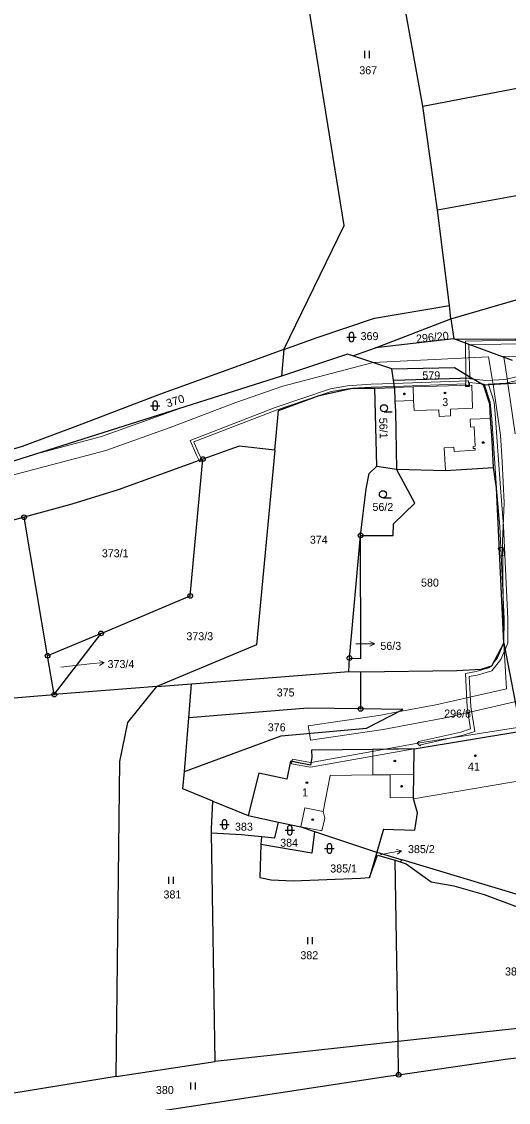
# Model space of a CAD drawing. Extents: x -769392 to -767038, y -1018329 to -1015269.
# Drawn here: x -768677.7 to -768574.3, y -1016436.2 to -1016206.6 of the extents above; entities that cross this region are included whole.
import ezdxf
from ezdxf.enums import TextEntityAlignment as Align

# ---------------------------------------------------------------- set-up
doc = ezdxf.new("R2010")
doc.units = 0
doc.header["$LTSCALE"] = 0.68
for name, color, linetype, lineweight in [('1', 7, 'Continuous', 25), ('13', 7, 'Continuous', 13), ('3', 7, 'Continuous', 25), ('4', 7, 'Continuous', 13), ('5', 7, 'Continuous', 25), ('7', 7, 'Continuous', 13), ('8', 7, 'Continuous', 25)]:
    doc.layers.add(name, color=color, linetype=linetype, lineweight=lineweight)
doc.layers.add('2', color=7, linetype='Continuous')

msp = doc.modelspace()

# ---------------------------------------------------------------- linework, layer by layer
at = {"layer": '1'}
for p, q in [((-768592.42, -1016224.53), (-768596.46, -1016202.24)), ((-768592.42, -1016224.53), (-768551.7, -1016216.69)), ((-768589.35, -1016246.59), (-768592.42, -1016224.53)), ((-768557.84, -1016240.9), (-768589.35, -1016246.59)), ((-768586.82, -1016266.89), (-768589.35, -1016246.59)), ((-768586.47, -1016269.73), (-768586.82, -1016266.89)), ((-768586.47, -1016269.73), (-768572.62, -1016265.7)), ((-768602.49, -1016275.85), (-768586.47, -1016269.73)), ((-768586.47, -1016269.73), (-768585.84, -1016273.96)), ((-768585.84, -1016273.96), (-768602.49, -1016275.85)), ((-768573.42, -1016278.56), (-768585.84, -1016273.96)), ((-768585.84, -1016273.96), (-768559.15, -1016274.1)), ((-768621.96, -1016276.21), (-768622.48, -1016281.86)), ((-768607.35, -1016277.6), (-768602.49, -1016275.85)), ((-768599.04, -1016280.32), (-768607.35, -1016277.6)), ((-768599.04, -1016280.32), (-768585.73, -1016280.07)), ((-768598.72, -1016282.72), (-768599.04, -1016280.32)), ((-768585.73, -1016280.07), (-768582.11, -1016282.22)), ((-768598.72, -1016282.72), (-768582.11, -1016282.22)), ((-768598.51, -1016284.32), (-768598.72, -1016282.72)), ((-768582.11, -1016282.22), (-768579.53, -1016283.75)), ((-768579.53, -1016283.75), (-768569.79, -1016283.19)), ((-768602.65, -1016284.41), (-768598.51, -1016284.32)), ((-768602.24, -1016301.02), (-768602.65, -1016284.41)), ((-768598.51, -1016284.32), (-768598.39, -1016287.19)), ((-768578.2, -1016287.85), (-768579.53, -1016283.75)), ((-768598.39, -1016287.19), (-768598.28, -1016289.32)), ((-768578.09, -1016290.87), (-768578.2, -1016287.85)), ((-768598.28, -1016289.32), (-768598.05, -1016301.67)), ((-768577.73, -1016295.5), (-768578.09, -1016290.87)), ((-768631.49, -1016296.74), (-768639.19, -1016299.52)), ((-768623.94, -1016297.62), (-768631.49, -1016296.74)), ((-768577.47, -1016301.28), (-768577.73, -1016295.5)), ((-768639.19, -1016299.52), (-768657.22, -1016306.04)), ((-768641.88, -1016328.59), (-768639.19, -1016299.52)), ((-768602.24, -1016301.02), (-768598.05, -1016301.67)), ((-768598.05, -1016301.67), (-768587.63, -1016301.96)), ((-768594.12, -1016308.89), (-768598.05, -1016301.67)), ((-768587.63, -1016301.96), (-768577.47, -1016301.28)), ((-768576.83, -1016305.58), (-768577.47, -1016301.28)), ((-768657.22, -1016306.04), (-768667.08, -1016309.08)), ((-768575.23, -1016338.61), (-768576.83, -1016305.58)), ((-768667.08, -1016309.08), (-768677.21, -1016311.87)), ((-768598.68, -1016313.23), (-768594.12, -1016308.89)), ((-768677.21, -1016311.87), (-768686.93, -1016314.55)), ((-768672.19, -1016341.29), (-768677.21, -1016311.87)), ((-768598.78, -1016315.77), (-768598.68, -1016313.23)), ((-768608.05, -1016341.79), (-768605.68, -1016315.72)), ((-768605.68, -1016315.72), (-768598.78, -1016315.77)), ((-768605.62, -1016341.85), (-768605.68, -1016315.72)), ((-768660.84, -1016336.55), (-768641.88, -1016328.59)), ((-768660.84, -1016336.55), (-768672.19, -1016341.29)), ((-768670.77, -1016349.54), (-768660.84, -1016336.55)), ((-768577.76, -1016343.44), (-768575.23, -1016338.61)), ((-768575.23, -1016338.61), (-768571.6, -1016357.31)), ((-768670.77, -1016349.54), (-768672.19, -1016341.29)), ((-768608.18, -1016344.65), (-768608.05, -1016341.79)), ((-768608.05, -1016341.79), (-768605.62, -1016341.85)), ((-768641.59, -1016347.26), (-768608.18, -1016344.65)), ((-768608.18, -1016344.65), (-768605.68, -1016344.71)), ((-768605.68, -1016344.71), (-768605.69, -1016352.6)), ((-768605.68, -1016344.71), (-768585.23, -1016344.42)), ((-768585.23, -1016344.42), (-768580.06, -1016344.17)), ((-768580.06, -1016344.17), (-768577.76, -1016343.44)), ((-768648.98, -1016347.83), (-768641.59, -1016347.26)), ((-768642.16, -1016354.47), (-768641.59, -1016347.26)), ((-768712.03, -1016352.77), (-768670.77, -1016349.54)), ((-768648.98, -1016347.83), (-768670.77, -1016349.54)), ((-768643.08, -1016365.89), (-768642.16, -1016354.47)), ((-768594.29, -1016361.09), (-768571.6, -1016357.31)), ((-768603.09, -1016361.21), (-768616.13, -1016361.33)), ((-768616.13, -1016361.33), (-768616.02, -1016362.93)), ((-768594.29, -1016361.09), (-768603.09, -1016361.21)), ((-768594.38, -1016366.52), (-768594.29, -1016361.09)), ((-768620.57, -1016363.7), (-768621.35, -1016367.52)), ((-768616.32, -1016364.51), (-768620.57, -1016363.7)), ((-768616.02, -1016362.93), (-768616.32, -1016364.51)), ((-768627.31, -1016366.26), (-768629.54, -1016375.23)), ((-768621.35, -1016367.52), (-768627.31, -1016366.26)), ((-768594.46, -1016371.32), (-768594.38, -1016366.52)), ((-768637.05, -1016372.2), (-768629.54, -1016375.23)), ((-768594.45, -1016371.67), (-768594.46, -1016371.32)), ((-768593.61, -1016374.68), (-768594.45, -1016371.67)), ((-768629.54, -1016375.23), (-768623.13, -1016376.62)), ((-768594.12, -1016378.36), (-768593.61, -1016374.68)), ((-768623.13, -1016376.62), (-768618.4, -1016377.64)), ((-768618.4, -1016377.64), (-768615.5, -1016378.61)), ((-768636.6, -1016427.52), (-768637.35, -1016378.93)), ((-768626.73, -1016379.72), (-768626.91, -1016381.42)), ((-768615.5, -1016378.61), (-768602.49, -1016382.96)), ((-768600.8, -1016378.13), (-768602.21, -1016383.04)), ((-768600.8, -1016378.13), (-768594.12, -1016378.36)), ((-768602.21, -1016383.04), (-768603.78, -1016388.43)), ((-768602.49, -1016382.96), (-768602.21, -1016383.04)), ((-768602.21, -1016383.04), (-768596.87, -1016384.66)), ((-768597.72, -1016423.25), (-768598.32, -1016384.76)), ((-768596.87, -1016384.66), (-768597.3, -1016385.07)), ((-768571.23, -1016392.4), (-768596.87, -1016384.66)), ((-768515.42, -1016414.21), (-768597.72, -1016423.25)), ((-768597.72, -1016423.25), (-768636.6, -1016427.52)), ((-768597.61, -1016430.31), (-768597.72, -1016423.25)), ((-768657.6, -1016430.72), (-768636.6, -1016427.52)), ((-768657.6, -1016430.72), (-768699.1, -1016437.44))]:
    msp.add_line(p, q, dxfattribs=at)
for points in [[(-768621.96, -1016276.21), (-768609.16, -1016249.91), (-768617.69, -1016197.27), (-768590.44, -1016160.65)], [(-768621.96, -1016276.21), (-768614.91, -1016273.67), (-768602.73, -1016269.59), (-768586.82, -1016266.89)], [(-768621.96, -1016276.21), (-768630.81, -1016279.41), (-768648.44, -1016285.81), (-768665.84, -1016292.42), (-768677.61, -1016296.82), (-768689.85, -1016300.54), (-768706.04, -1016305.61), (-768723.63, -1016310.87)], [(-768607.35, -1016277.6), (-768608.47, -1016277.23), (-768622.48, -1016281.86)], [(-768622.48, -1016281.86), (-768683.8, -1016301.28), (-768723.63, -1016310.87)], [(-768623.94, -1016297.62), (-768623.16, -1016289.18), (-768614.47, -1016286), (-768607.38, -1016284.46), (-768602.65, -1016284.41)], [(-768623.94, -1016297.62), (-768627.77, -1016338.94), (-768648.98, -1016347.83)], [(-768605.68, -1016315.72), (-768604.47, -1016305.83), (-768603.85, -1016302.57), (-768602.24, -1016301.02)], [(-768657.6, -1016430.72), (-768656.85, -1016363.77), (-768655.17, -1016355.5), (-768648.98, -1016347.83)], [(-768643.08, -1016365.89), (-768622.57, -1016358.32), (-768604.43, -1016356.68), (-768596.71, -1016352.7), (-768605.69, -1016352.6)], [(-768605.69, -1016352.6), (-768616.9, -1016352.46), (-768642.16, -1016354.47)], [(-768637.05, -1016372.2), (-768643.47, -1016369.6), (-768643.08, -1016365.89)], [(-768637.35, -1016378.93), (-768637.36, -1016378.08), (-768637.05, -1016372.2)], [(-768626.73, -1016379.72), (-768623.93, -1016380.01), (-768623.13, -1016376.62)], [(-768637.35, -1016378.93), (-768630.98, -1016379.26), (-768626.73, -1016379.72)], [(-768615.5, -1016378.61), (-768616.02, -1016383.21), (-768626.91, -1016381.42)], [(-768626.91, -1016381.42), (-768627.07, -1016388.41), (-768624.68, -1016388.89), (-768620.01, -1016389.13), (-768605.69, -1016388.54), (-768603.78, -1016388.43)], [(-768603.78, -1016388.43), (-768602.06, -1016383.63), (-768598.32, -1016384.76), (-768597.3, -1016385.07)], [(-768597.3, -1016385.07), (-768595.97, -1016385.47), (-768590.69, -1016389.34), (-768585.89, -1016390.17), (-768579.44, -1016391.99), (-768554.41, -1016401.35), (-768536.99, -1016407.59), (-768527.09, -1016410.45), (-768515.42, -1016414.21)], [(-768597.61, -1016430.31), (-768574.91, -1016427.03), (-768544.97, -1016423.27), (-768527.49, -1016419.91), (-768510.33, -1016417.43)], [(-768697.86, -1016445.59), (-768599.92, -1016430.64), (-768597.61, -1016430.31)]]:
    msp.add_lwpolyline(points, dxfattribs=at)
at = {"layer": '13'}
for points in [[(-768699.64, -1016308.19), (-768659.83, -1016297.71), (-768646.13, -1016292.81), (-768632.17, -1016287.45), (-768622.22, -1016284.01), (-768603.02, -1016279.02), (-768578.47, -1016277.79), (-768577.72, -1016282.36), (-768577.53, -1016283.64), (-768574.38, -1016283.45), (-768574.61, -1016281.88), (-768575.27, -1016277.87), (-768585.84, -1016273.96), (-768602.49, -1016275.85), (-768607.347, -1016277.599), (-768608.47, -1016277.23), (-768622.48, -1016281.86), (-768642.32, -1016288.14), (-768660.75, -1016294.73), (-768674.85, -1016298.44), (-768683.8, -1016301.28)], [(-768572.83, -1016294.11), (-768574.38, -1016283.45), (-768577.53, -1016283.64), (-768575.96, -1016294.45), (-768575.58, -1016300.01), (-768575.19, -1016308.81), (-768575.49, -1016316.99), (-768575.46, -1016323.44), (-768575.28, -1016337.49), (-768575.23, -1016338.61), (-768575.27, -1016338.68), (-768574.67, -1016348.34), (-768589.7, -1016351.7), (-768597.74, -1016353.23), (-768601.41, -1016353.93), (-768616.81, -1016356.18), (-768616.56, -1016357.78), (-768616.33, -1016359.25), (-768600.89, -1016356.99), (-768587.74, -1016354.48), (-768572.31, -1016350.97)], [(-768569.72, -1016281.3), (-768574.97, -1016282.6), (-768579.08, -1016282.81), (-768581.59, -1016282.53), (-768579.91, -1016283.52), (-768579.4, -1016283.58), (-768579.35, -1016283.74), (-768578.52, -1016283.69), (-768578.56, -1016283.58), (-768574.85, -1016283.4), (-768569.87, -1016282.17)], [(-768541.64, -1016351.71), (-768593.54, -1016359.85), (-768600.9, -1016361.18), (-768594.29, -1016361.09), (-768571.6, -1016357.31)]]:
    msp.add_lwpolyline(points, dxfattribs=at)
for points in [[(-768562.71, -1016277.52), (-768560.04, -1016277.46), (-768559.31, -1016277.38), (-768559.15, -1016274.1), (-768585.84, -1016273.96), (-768575.27, -1016277.87), (-768575.3, -1016277.7)], [(-768583.42, -1016274.43), (-768583.41, -1016274.86), (-768582.47, -1016275.21), (-768572.49, -1016275.05), (-768571.9, -1016274.64), (-768571.31, -1016274.6), (-768570.93, -1016274.92), (-768562.98, -1016274.76), (-768562.81, -1016274.11), (-768563.03, -1016274.11), (-768563.02, -1016273.92), (-768563.37, -1016273.91), (-768563.38, -1016274.12), (-768570.5, -1016274.24), (-768571.05, -1016273.78), (-768572.17, -1016273.86), (-768572.75, -1016274.25)], [(-768583.41, -1016274.86), (-768583.32, -1016281.5), (-768582.45, -1016282.02), (-768582.66, -1016275.21), (-768582.47, -1016275.21)], [(-768598.62, -1016283.45), (-768603.46, -1016283.62), (-768608.48, -1016283.96), (-768612.1, -1016284.57), (-768623.84, -1016288.56), (-768641.89, -1016295.53), (-768640.59, -1016298.64), (-768640, -1016299.81), (-768639.43, -1016299.61), (-768640.05, -1016298.39), (-768641.1, -1016295.87), (-768623.63, -1016289.12), (-768614.47, -1016286), (-768611.95, -1016285.15), (-768608.41, -1016284.55), (-768607.38, -1016284.46), (-768603.43, -1016284.22), (-768598.55, -1016284.05)], [(-768598.62, -1016283.45), (-768598.55, -1016284.05), (-768583.3, -1016283.53), (-768583.28, -1016283.86), (-768582.68, -1016283.84), (-768582.75, -1016282.91)], [(-768583.37, -1016284.07), (-768582.56, -1016284.05), (-768582.52, -1016283.23), (-768579.91, -1016283.52), (-768581.59, -1016282.53), (-768582.44, -1016282.43), (-768582.45, -1016282.02), (-768583.32, -1016281.5), (-768583.3, -1016282.76)], [(-768579.35, -1016283.74), (-768578.14, -1016287.43), (-768577.78, -1016290.99), (-768576.77, -1016305.69), (-768576.1, -1016313.83), (-768575.19, -1016333.44), (-768575.21, -1016338.45), (-768575.23, -1016338.51), (-768575.23, -1016338.61), (-768575.46, -1016339.06), (-768576.57, -1016341.7), (-768577.36, -1016342.68), (-768577.76, -1016343.44), (-768578.05, -1016343.53), (-768578.25, -1016343.78), (-768581.11, -1016344.66), (-768583.42, -1016345.04), (-768583.04, -1016352.19), (-768582.29, -1016356.84), (-768584.36, -1016357.5), (-768593.3, -1016359.49), (-768593.67, -1016359.88), (-768593.09, -1016360.43), (-768592.88, -1016360.22), (-768584.15, -1016358.27), (-768581.39, -1016357.39), (-768582.25, -1016352.11), (-768582.59, -1016345.72), (-768580.92, -1016345.44), (-768577.78, -1016344.47), (-768575.87, -1016342.11), (-768574.41, -1016338.61), (-768574.39, -1016333.42), (-768575.3, -1016313.77), (-768575.98, -1016305.63), (-768576.98, -1016290.91), (-768577.32, -1016287.38), (-768578.52, -1016283.69)], [(-768640, -1016299.81), (-768639.89, -1016300.09), (-768639.32, -1016299.89), (-768639.43, -1016299.61)], [(-768576.21, -1016318.43), (-768576.43, -1016318.44), (-768576.41, -1016318.79), (-768576.19, -1016318.78)], [(-768576.19, -1016318.78), (-768576.18, -1016318.9), (-768575.88, -1016318.9), (-768575.73, -1016320.1), (-768575.13, -1016320.02), (-768575.36, -1016318.28), (-768576.21, -1016318.3), (-768576.21, -1016318.43)], [(-768594.29, -1016361.09), (-768600.9, -1016361.18), (-768616.21, -1016363.95), (-768616.32, -1016364.51), (-768620.27, -1016363.76), (-768620.36, -1016364.25), (-768616.34, -1016364.99)], [(-768616.32, -1016364.51), (-768616.21, -1016363.95), (-768616.34, -1016363.97), (-768620.18, -1016363.26), (-768620.27, -1016363.76)]]:
    msp.add_lwpolyline(points, close=True, dxfattribs=at)
at = {"layer": '3'}
for p, q in [((-768604.761, -1016214.3), (-768604.761, -1016212.8)), ((-768603.76, -1016214.3), (-768603.76, -1016212.8)), ((-768608.621, -1016273.581), (-768606.619, -1016273.581)), ((-768608.121, -1016273.081), (-768608.121, -1016274.082)), ((-768607.119, -1016274.082), (-768607.119, -1016273.081)), ((-768649.861, -1016287.661), (-768649.861, -1016288.662)), ((-768648.859, -1016288.662), (-768648.859, -1016287.661)), ((-768650.361, -1016288.161), (-768648.359, -1016288.161)), ((-768600.703, -1016289.45), (-768598.953, -1016289.45)), ((-768600.943, -1016307.72), (-768599.193, -1016307.72)), ((-768635.601, -1016377.131), (-768633.599, -1016377.131)), ((-768635.101, -1016376.631), (-768635.101, -1016377.632)), ((-768634.099, -1016377.632), (-768634.099, -1016376.631)), ((-768621.741, -1016378.361), (-768619.739, -1016378.361)), ((-768621.241, -1016377.861), (-768621.241, -1016378.862)), ((-768620.239, -1016378.862), (-768620.239, -1016377.861)), ((-768612.821, -1016381.751), (-768612.821, -1016382.752)), ((-768611.819, -1016382.752), (-768611.819, -1016381.751)), ((-768613.321, -1016382.251), (-768611.319, -1016382.251)), ((-768646.421, -1016389.78), (-768646.421, -1016388.28)), ((-768645.42, -1016389.78), (-768645.42, -1016388.28)), ((-768616.921, -1016402.58), (-768616.921, -1016401.08)), ((-768615.92, -1016402.58), (-768615.92, -1016401.08)), ((-768641.771, -1016433.48), (-768641.771, -1016431.98)), ((-768640.77, -1016433.48), (-768640.77, -1016431.98))]:
    msp.add_line(p, q, dxfattribs=at)
for centre in [(-768600.7029, -1016288.6998), (-768600.9429, -1016306.9698)]:
    msp.add_circle(centre, 0.75, dxfattribs=at)
for centre, start, end in [((-768607.62, -1016273.0809), 0, 180), ((-768607.62, -1016274.0809), 180, 359.98789), ((-768649.36, -1016287.6609), 0, 180), ((-768649.36, -1016288.6609), 180, 359.98789), ((-768634.6, -1016376.6309), 0, 180), ((-768634.6, -1016377.6309), 180, 359.98789), ((-768620.74, -1016377.8609), 0, 180), ((-768620.74, -1016378.8609), 180, 359.98789), ((-768612.32, -1016381.7509), 0, 180), ((-768612.32, -1016382.7509), 180, 359.98789)]:
    msp.add_arc(centre, 0.5, start, end, dxfattribs=at)
at = {"layer": '4'}
for p, q in [((-768598.51, -1016284.32), (-768594.49, -1016284.19)), ((-768582.06, -1016283.82), (-768594.49, -1016284.19)), ((-768594.49, -1016284.19), (-768594.43, -1016287.06)), ((-768581.91, -1016288.7), (-768582.06, -1016283.82)), ((-768594.43, -1016287.06), (-768598.39, -1016287.19)), ((-768594.43, -1016287.06), (-768594.28, -1016289.2)), ((-768594.28, -1016289.2), (-768589.09, -1016289.01)), ((-768589.09, -1016289.01), (-768589, -1016290.44)), ((-768589, -1016290.44), (-768586.55, -1016290.33)), ((-768586.61, -1016288.92), (-768581.91, -1016288.7)), ((-768586.55, -1016290.33), (-768586.61, -1016288.92)), ((-768578.09, -1016290.87), (-768582.38, -1016291.05)), ((-768582.38, -1016291.05), (-768582.33, -1016292.7)), ((-768582.33, -1016292.7), (-768581.53, -1016292.66)), ((-768581.53, -1016292.66), (-768581.35, -1016296.77)), ((-768585.89, -1016297), (-768587.89, -1016297.15)), ((-768587.89, -1016297.15), (-768587.63, -1016301.96)), ((-768585.83, -1016297.88), (-768585.89, -1016297)), ((-768581.35, -1016296.77), (-768581.79, -1016296.81)), ((-768581.79, -1016296.81), (-768581.78, -1016297.26)), ((-768581.78, -1016297.26), (-768581.33, -1016297.27)), ((-768581.33, -1016297.27), (-768581.31, -1016297.62)), ((-768581.31, -1016297.62), (-768585.83, -1016297.88)), ((-768603.1, -1016366.61), (-768603.09, -1016361.21)), ((-768613.66, -1016374.42), (-768612.18, -1016366.71)), ((-768612.18, -1016366.71), (-768603.1, -1016366.61)), ((-768603.1, -1016366.61), (-768599.4, -1016366.57)), ((-768599.4, -1016366.57), (-768599.41, -1016371.51)), ((-768599.4, -1016366.57), (-768594.38, -1016366.52)), ((-768594.45, -1016371.67), (-768569.79, -1016367.55)), ((-768599.41, -1016371.51), (-768594.46, -1016371.32)), ((-768618.4, -1016377.64), (-768617.53, -1016373.63)), ((-768617.53, -1016373.63), (-768613.66, -1016374.42)), ((-768613.66, -1016374.42), (-768613.29, -1016375.78)), ((-768613.9, -1016378.49), (-768618.4, -1016377.64)), ((-768613.29, -1016375.78), (-768613.9, -1016378.49))]:
    msp.add_line(p, q, dxfattribs=at)
at = {"layer": '5'}
for centre in [(-768596.3868, -1016285.6592), (-768587.7268, -1016285.4592), (-768579.6268, -1016295.9892), (-768598.4068, -1016363.6392), (-768581.2868, -1016362.5492), (-768617.0968, -1016368.2592), (-768596.9568, -1016369.0092), (-768615.8668, -1016376.1192)]:
    msp.add_circle(centre, 0.175, dxfattribs=at)
at = {"layer": '7'}
for p, q in [((-768602.689, -1016338.77), (-768603.69, -1016338.269)), ((-768660.205, -1016342.726), (-768661.254, -1016342.333)), ((-768596.955, -1016382.749), (-768598.028, -1016382.43))]:
    msp.add_line(p, q, dxfattribs=at)
for points in [[(-768606.68, -1016338.77), (-768605.69, -1016338.77), (-768602.689, -1016338.77), (-768603.69, -1016339.271)], [(-768669.38, -1016343.73), (-768663.19, -1016343.04), (-768660.205, -1016342.726), (-768661.149, -1016343.329)], [(-768601.52, -1016383.57), (-768599.91, -1016383.27), (-768596.955, -1016382.749), (-768597.854, -1016383.416)]]:
    msp.add_lwpolyline(points, dxfattribs=at)
at = {"layer": '8'}
for centre, radius in [((-768639.19, -1016299.5199), 0.5), ((-768639.19, -1016299.5199), 0.0303), ((-768677.21, -1016311.8699), 0.5), ((-768677.21, -1016311.8699), 0.0303), ((-768605.68, -1016315.7199), 0.5), ((-768605.68, -1016315.7199), 0.0303), ((-768641.88, -1016328.5899), 0.5), ((-768641.88, -1016328.5899), 0.0303), ((-768660.84, -1016336.5499), 0.5), ((-768660.84, -1016336.5499), 0.0303), ((-768672.19, -1016341.2899), 0.5), ((-768672.19, -1016341.2899), 0.0303), ((-768608.05, -1016341.7899), 0.5), ((-768608.05, -1016341.7899), 0.0303), ((-768670.77, -1016349.5399), 0.5), ((-768670.77, -1016349.5399), 0.0303), ((-768605.69, -1016352.5999), 0.5), ((-768605.69, -1016352.5999), 0.0303), ((-768597.61, -1016430.3099), 0.5), ((-768597.61, -1016430.3099), 0.0303)]:
    msp.add_circle(centre, radius, dxfattribs=at)

# ---------------------------------------------------------------- texts
at = {"layer": '2'}
for s, p in [('367', (-768605.96, -1016217.745)), ('369', (-768605.68, -1016274.235)), ('374', (-768616.46, -1016317.485)), ('373/4', (-768659.46, -1016343.912)), ('375', (-768623.51, -1016349.945)), ('376', (-768625.41, -1016357.345)), ('383', (-768632.38, -1016378.465)), ('384', (-768622.78, -1016381.875)), ('385/1', (-768612.13, -1016387.345)), ('381', (-768647.57, -1016392.865)), ('382', (-768618.48, -1016405.775)), ('387', (-768574.99, -1016409.225)), ('380', (-768649.18, -1016434.405))]:
    msp.add_text(s, height=1.7, dxfattribs=at).set_placement(p)
for s, rotation, p in [('296/20', 6, (-768590.3393, -1016274.4479)), ('56/1', 272, (-768601.6735, -1016292.9693))]:
    msp.add_text(s, height=1.7, rotation=rotation, dxfattribs=at).set_placement(p, align=Align.CENTER)
for s, p in [('579', (-768590.659, -1016282.555)), ('3', (-768587.7, -1016288.255)), ('56/2', (-768600.949, -1016310.525)), ('373/1', (-768657.83, -1016320.365)), ('580', (-768590.939, -1016326.605)), ('373/3', (-768639.86, -1016337.995)), ('56/3', (-768599.269, -1016340.045)), ('296/8', (-768585.07, -1016354.425)), ('41', (-768581.609, -1016365.675)), ('1', (-768617.48, -1016371.175)), ('385/2', (-768592.77, -1016383.225))]:
    msp.add_text(s, height=1.7, dxfattribs=at).set_placement(p, align=Align.CENTER)
at = {"layer": '2', "width": 1.05}
msp.add_text('370', height=1.7, rotation=17, dxfattribs=at).set_placement((-768646.735, -1016288.546))

doc.saveas('drawing.dxf')
